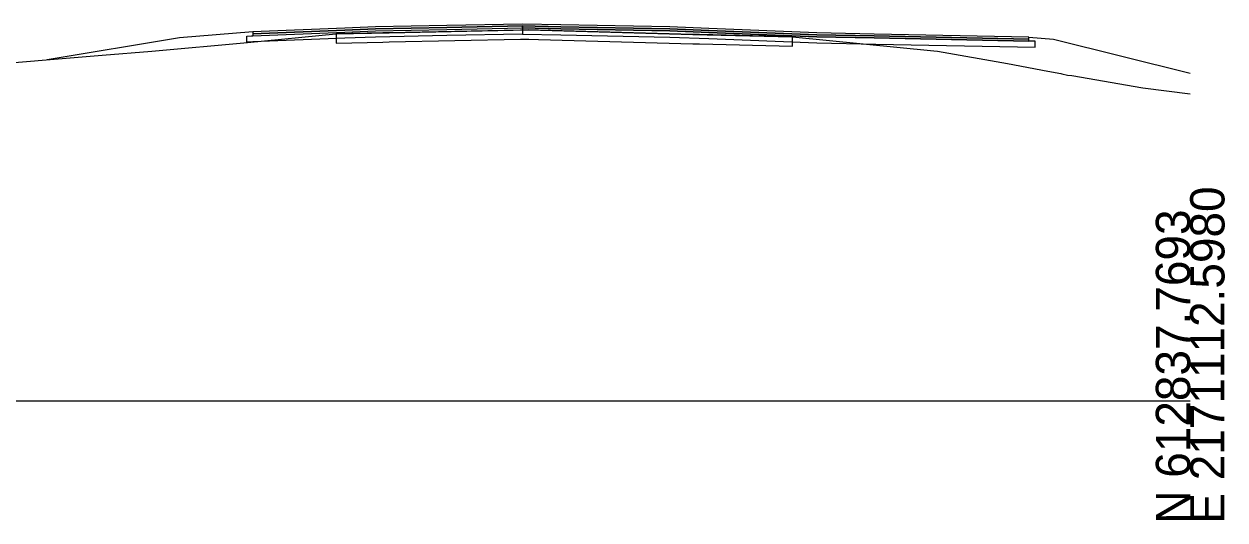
# Model space of a CAD drawing. Extents: x -26 to 1303, y -3010 to 12038.
# Drawn here: x 204.9 to 302.8, y 6490.3 to 6530.7 of the extents above; entities that cross this region are included whole.
import ezdxf

# ---------------------------------------------------------------- set-up
doc = ezdxf.new("R2010")
doc.units = 0
for name, color, linetype in [('RD_GPK_XS_Cell', 7, 'Continuous'), ('RD_XS_Base', 7, 'Continuous'), ('RD_XS_ExGround', 7, 'Continuous'), ('RD_XS_ExPaveRet', 7, 'Continuous'), ('RD_XS_Greenside', 7, 'Continuous'), ('RD_XS_Pave', 7, 'Continuous'), ('RD_XS_PaveOvlay_CP', 7, 'Continuous'), ('RD_XS_TieSlope', 7, 'Continuous')]:
    doc.layers.add(name, color=color, linetype=linetype)

msp = doc.modelspace()

# ---------------------------------------------------------------- linework, layer by layer
at = {"layer": 'RD_GPK_XS_Cell'}
msp.add_line((150, 6500), (300, 6500), dxfattribs=at)
at = {"layer": 'RD_XS_Base'}
for p, q in [((231.039, 6530.056), (233.547, 6530.156)), ((233.547, 6530.156), (239.358, 6530.272)), ((239.358, 6530.272), (245.547, 6530.396)), ((245.547, 6530.514), (245.547, 6530.555)), ((245.547, 6530.555), (245.547, 6530.384)), ((245.547, 6530.396), (245.547, 6530.514)), ((245.547, 6530.396), (245.547, 6530.396)), ((248.679, 6530.333), (245.547, 6530.396)), ((245.547, 6530.396), (245.547, 6530.396)), ((245.547, 6530.396), (245.547, 6530.266)), ((245.547, 6530.384), (245.547, 6529.896)), ((245.547, 6530.266), (245.547, 6529.896)), ((257.547, 6530.156), (248.679, 6530.333)), ((260.729, 6530.029), (257.547, 6530.156)), ((223.047, 6529.736), (223.423, 6529.751)), ((223.047, 6529.612), (223.047, 6529.736)), ((223.047, 6529.236), (223.047, 6529.612)), ((223.423, 6529.251), (223.047, 6529.236)), ((223.423, 6529.751), (223.547, 6529.756)), ((223.547, 6529.256), (223.423, 6529.251)), ((223.547, 6529.756), (231.039, 6530.056)), ((231.039, 6529.556), (223.547, 6529.256)), ((233.547, 6529.656), (231.039, 6529.556)), ((239.358, 6529.772), (233.547, 6529.656)), ((245.547, 6529.896), (239.358, 6529.772)), ((245.547, 6529.896), (248.679, 6529.833)), ((248.679, 6529.833), (257.547, 6529.656)), ((257.547, 6529.656), (260.729, 6529.529)), ((269.547, 6529.676), (260.729, 6530.029)), ((260.729, 6529.529), (269.547, 6529.176)), ((274.216, 6529.583), (269.547, 6529.676)), ((269.547, 6529.176), (274.351, 6529.08)), ((286.847, 6529.33), (274.216, 6529.583)), ((286.984, 6529.327), (286.847, 6529.33)), ((287.347, 6529.32), (286.984, 6529.327)), ((287.347, 6529.183), (287.347, 6529.32)), ((287.347, 6528.82), (287.347, 6529.183)), ((274.351, 6529.08), (287.347, 6528.82))]:
    msp.add_line(p, q, dxfattribs=at)
at = {"layer": 'RD_XS_ExGround'}
msp.add_lwpolyline([(200.495, 6527.27), (211.256, 6528.175), (215.292, 6528.501), (223.098, 6529.221), (230.326, 6529.919), (234.661, 6530.01), (246.055, 6530.236), (259.421, 6529.865), (267.557, 6529.664), (279.099, 6528.529), (279.388, 6528.501), (285.093, 6527.497), (288.383, 6526.866), (289.449, 6526.687), (289.531, 6526.667), (289.984, 6526.554), (290.344, 6526.515), (296.127, 6525.505), (300, 6525.025)], dxfattribs=at)
at = {"layer": 'RD_XS_ExPaveRet'}
for p, q in [((245.366, 6530.223), (234.661, 6530.01)), ((259.977, 6529.852), (259.421, 6529.865)), ((267.557, 6529.664), (259.977, 6529.852))]:
    msp.add_line(p, q, dxfattribs=at)
for points in [[(259.421, 6529.865), (246.839, 6530.215), (246.055, 6530.236), (245.366, 6530.223), (234.661, 6530.01), (234.133, 6529.999), (230.327, 6529.919), (230.327, 6529.237), (230.327, 6529.169), (234.133, 6529.249), (234.661, 6529.26), (245.366, 6529.473), (246.055, 6529.486), (246.839, 6529.465), (259.421, 6529.115), (259.977, 6529.102), (267.557, 6528.914), (267.557, 6529.631), (267.557, 6529.664), (259.977, 6529.852), (259.421, 6529.865)], [(259.421, 6529.865), (246.839, 6530.215), (246.055, 6530.236), (245.366, 6530.223)], [(234.661, 6530.01), (234.133, 6529.999), (230.327, 6529.919)], [(230.327, 6529.919), (230.327, 6529.237), (230.327, 6529.169), (234.133, 6529.249), (234.661, 6529.26), (245.366, 6529.473), (246.055, 6529.486), (246.839, 6529.465), (259.421, 6529.115), (259.977, 6529.102), (267.557, 6528.914), (267.557, 6529.631), (267.557, 6529.664)]]:
    msp.add_lwpolyline(points, dxfattribs=at)
at = {"layer": 'RD_XS_Greenside'}
for p, q in [((217.547, 6529.594), (206.769, 6527.798)), ((288.847, 6529.488), (300, 6526.7))]:
    msp.add_line(p, q, dxfattribs=at)
at = {"layer": 'RD_XS_Pave'}
for p, q in [((231.039, 6530.374), (223.547, 6530.074)), ((231.039, 6530.215), (223.547, 6529.915)), ((223.547, 6529.915), (231.039, 6530.215)), ((233.547, 6530.474), (231.039, 6530.374)), ((233.547, 6530.315), (231.039, 6530.215)), ((231.039, 6530.215), (233.547, 6530.315)), ((231.039, 6530.056), (233.547, 6530.156)), ((239.358, 6530.59), (233.547, 6530.474)), ((239.358, 6530.431), (233.547, 6530.315)), ((233.547, 6530.315), (239.358, 6530.431)), ((233.547, 6530.156), (239.358, 6530.272)), ((245.547, 6530.714), (239.358, 6530.59)), ((245.547, 6530.555), (239.358, 6530.431)), ((239.358, 6530.431), (245.547, 6530.555)), ((239.358, 6530.272), (245.547, 6530.396)), ((248.679, 6530.651), (245.547, 6530.714)), ((245.547, 6530.514), (245.547, 6530.555)), ((245.547, 6530.555), (248.679, 6530.492)), ((248.679, 6530.492), (245.547, 6530.555)), ((245.547, 6530.555), (245.547, 6530.555)), ((245.547, 6530.555), (245.547, 6530.555)), ((245.547, 6530.555), (245.547, 6530.514)), ((245.547, 6530.396), (245.547, 6530.514)), ((245.547, 6530.514), (245.547, 6530.396)), ((245.547, 6530.396), (245.547, 6530.396)), ((245.547, 6530.396), (245.547, 6530.396)), ((245.547, 6530.396), (248.679, 6530.333)), ((257.547, 6530.474), (248.679, 6530.651)), ((248.679, 6530.492), (257.547, 6530.315)), ((257.547, 6530.315), (248.679, 6530.492)), ((248.679, 6530.333), (257.547, 6530.156)), ((260.729, 6530.347), (257.547, 6530.474)), ((257.547, 6530.315), (260.729, 6530.188)), ((260.729, 6530.188), (257.547, 6530.315)), ((257.547, 6530.156), (260.729, 6530.029)), ((269.547, 6529.994), (260.729, 6530.347)), ((260.729, 6530.188), (269.547, 6529.835)), ((269.547, 6529.835), (260.729, 6530.188)), ((223.547, 6530.074), (223.547, 6530.035)), ((223.547, 6529.756), (231.039, 6530.056)), ((223.547, 6530.035), (223.547, 6529.915)), ((223.547, 6529.915), (223.547, 6529.876)), ((223.547, 6529.876), (223.547, 6529.756)), ((260.729, 6530.029), (269.547, 6529.676)), ((274.216, 6529.901), (269.547, 6529.994)), ((269.547, 6529.835), (274.216, 6529.742)), ((274.216, 6529.742), (269.547, 6529.835)), ((269.547, 6529.676), (274.216, 6529.583)), ((286.847, 6529.648), (274.216, 6529.901)), ((274.216, 6529.742), (286.847, 6529.489)), ((286.847, 6529.489), (274.216, 6529.742)), ((274.216, 6529.583), (286.847, 6529.33)), ((286.847, 6529.604), (286.847, 6529.648)), ((286.847, 6529.489), (286.847, 6529.604)), ((286.847, 6529.445), (286.847, 6529.489)), ((286.847, 6529.33), (286.847, 6529.445))]:
    msp.add_line(p, q, dxfattribs=at)
at = {"layer": 'RD_XS_PaveOvlay_CP'}
for p, q in [((231.039, 6530.374), (223.547, 6530.074)), ((233.547, 6530.474), (231.039, 6530.374)), ((239.358, 6530.59), (233.547, 6530.474)), ((245.547, 6530.714), (239.358, 6530.59)), ((248.679, 6530.651), (245.547, 6530.714)), ((257.547, 6530.474), (248.679, 6530.651)), ((260.729, 6530.347), (257.547, 6530.474)), ((269.547, 6529.994), (260.729, 6530.347)), ((274.216, 6529.901), (269.547, 6529.994)), ((286.847, 6529.648), (274.216, 6529.901))]:
    msp.add_line(p, q, dxfattribs=at)
at = {"layer": 'RD_XS_TieSlope'}
for p, q in [((223.547, 6530.074), (217.547, 6529.594)), ((286.847, 6529.648), (288.847, 6529.488))]:
    msp.add_line(p, q, dxfattribs=at)

# ---------------------------------------------------------------- texts
at = {"layer": 'RD_GPK_XS_Cell'}
for s, p in [('E 2171112.5980', (302.8, 6490)), ('N 612837.7693', (300, 6490))]:
    msp.add_text(s, height=2.8, rotation=90, dxfattribs=at).set_placement(p)

doc.saveas('drawing.dxf')
